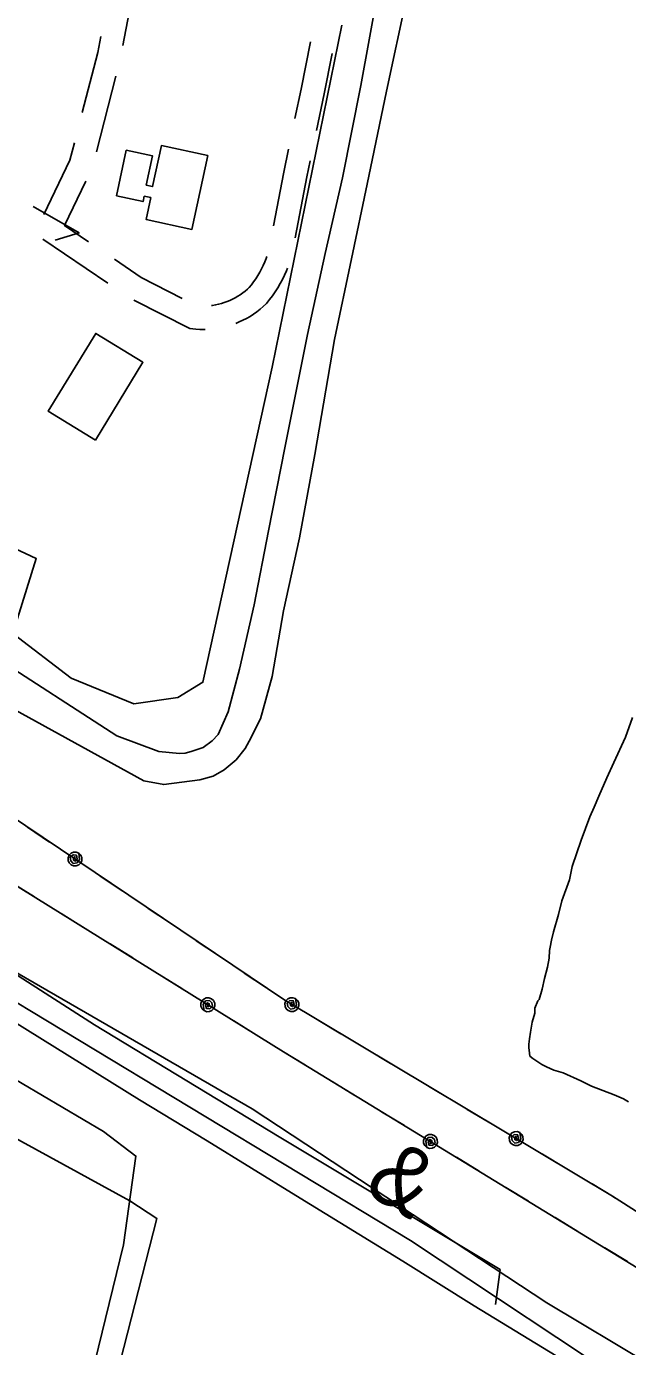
# Model space of a CAD drawing. Extents: x 3355677 to 3393573, y 612928 to 638357.
# Drawn here: x 3365699 to 3366468, y 627611 to 629298 of the extents above; entities that cross this region are included whole.
import ezdxf

# ---------------------------------------------------------------- set-up
doc = ezdxf.new("R2010")
doc.units = 0
for name, color, linetype in [('V-BLDG-OTLN', 7, 'Continuous'), ('V-RAIL-IDEN', 7, 'Continuous'), ('V-RAIL-TRAK', 7, 'Continuous'), ('V-ROAD-CNTR', 7, 'Continuous'), ('V-SITE-OTLN', 7, 'Continuous'), ('V-SITE-VEGE', 7, 'Continuous'), ('V-TOPO-SHOR', 7, 'Continuous'), ('V-UTIL-LINE', 7, 'Continuous')]:
    doc.layers.add(name, color=color, linetype=linetype)

msp = doc.modelspace()

# ---------------------------------------------------------------- linework, layer by layer
at = {"layer": 'V-BLDG-OTLN'}
for points in [[(3365814, 629081.9), (3365826.6, 629140.2), (3365860.4, 629132.9), (3365852.3, 629095.6), (3365860.3, 629093.8), (3365871.7, 629146.1), (3365930.9, 629133.3), (3365910.5, 629039), (3365851.9, 629051.7), (3365857.9, 629079.6), (3365849.7, 629081.3), (3365848.2, 629074.5)], [(3365787.1, 628769.8), (3365726.9, 628806.7), (3365787.7, 628906.1), (3365848, 628869.2)]]:
    msp.add_lwpolyline(points, close=True, dxfattribs=at)
at = {"layer": 'V-RAIL-TRAK'}
for points in [[(3365843.5, 627926.6), (3365193.4, 628330.6), (3364528.2, 628738.8), (3364216.4, 628928.8), (3364132.2, 628979.5)], [(3366499.2, 627524.5), (3366393.7, 627589), (3366271.7, 627663.7), (3366180.2, 627720.6), (3366043.4, 627804.5), (3365929.9, 627874.5), (3365843.5, 627926.6)]]:
    msp.add_lwpolyline(points, dxfattribs=at)
at = {"layer": 'V-ROAD-CNTR'}
for p, q in [((3365788.4, 629138.1), (3365813.4, 629235)), ((3365802.9, 628970.4), (3365720.1, 629026.4))]:
    msp.add_line(p, q, dxfattribs=at)
for points in [[(3365822.4, 629273.9), (3365840.6, 629369.7), (3365841.1, 629372.1)], [(3365770.4, 629188.5), (3365790.2, 629265), (3365794.1, 629285.6)], [(3366062.3, 629278.7), (3366050.2, 629218.1), (3366042.3, 629180.7)], [(3366089.9, 629263.6), (3366079.6, 629212.1), (3366069.9, 629165.6)], [(3365721.3, 629058.1), (3365754.7, 629127.6), (3365760.4, 629149.8)], [(3366034.2, 629141.5), (3366028, 629112.2), (3366014.9, 629043.4)], [(3366061.7, 629126.5), (3366057.5, 629106.3), (3366042.5, 629028.3)], [(3365778.5, 629023.2), (3365747.8, 629043.9), (3365775, 629100.6)], [(3365707.4, 629068.1), (3365766.4, 629034.6), (3365735.7, 629025.2)], [(3365898.1, 628950.9), (3365845.7, 628977.7), (3365811.6, 629000.8)], [(3366006.3, 629004.4), (3366005.5, 629002), (3366003.7, 628997.5), (3366001.8, 628993), (3365999.7, 628988.6), (3365997.4, 628984.3), (3365994.9, 628980.1), (3365992.3, 628976), (3365989.5, 628972.1), (3365986.6, 628968.2), (3365983.8, 628964.9), (3365981.5, 628962.7), (3365978.6, 628960.2), (3365975.6, 628957.8), (3365972.5, 628955.6), (3365969.2, 628953.5), (3365966, 628951.5), (3365962.6, 628949.8), (3365959.1, 628948.1), (3365955.6, 628946.7), (3365952, 628945.4), (3365948.3, 628944.2), (3365944.6, 628943.3), (3365940.9, 628942.5), (3365937.1, 628941.9), (3365935.8, 628941.7)], [(3366032.8, 628989.6), (3366031.5, 628986.1), (3366029.1, 628980.5), (3366026.4, 628975), (3366023.6, 628969.7), (3366020.5, 628964.4), (3366017.2, 628959.3), (3366013.7, 628954.3), (3366010, 628949.5), (3366005.8, 628944.4), (3366001.6, 628940.4), (3365997.7, 628937), (3365993.6, 628933.8), (3365989.4, 628930.8), (3365985, 628927.9), (3365980.5, 628925.3), (3365975.9, 628922.9), (3365971.2, 628920.7), (3365966.7, 628918.8)], [(3365927.7, 628911.1), (3365925.8, 628911), (3365920.6, 628911.1), (3365915.4, 628911.5), (3365907.8, 628912.3), (3365836.5, 628948.7)], [(3365413.6, 628007.8), (3365424.1, 628030.9), (3365443.6, 628076.1), (3365465.8, 628078.1), (3365504.1, 628059.4), (3365615.1, 627993.6), (3365797.7, 627886.5), (3365839, 627854.8), (3365823.1, 627741.6), (3365759, 627479.8), (3365705.6, 627265.5), (3365656.9, 627059.9), (3365561.6, 626679.7), (3365525.3, 626552.8)]]:
    msp.add_lwpolyline(points, dxfattribs=at)
at = {"layer": 'V-SITE-OTLN'}
for points in [[(3366102.4, 629299.9), (3366013, 628862.9), (3365924.7, 628460.4), (3365892.5, 628440.8), (3365836.3, 628432.9), (3365756.1, 628465.5), (3365681.4, 628522.5), (3365711.5, 628618.4), (3365663.9, 628640.5), (3365602.5, 628542.5), (3365338.5, 628679.9), (3365195.8, 628738.5), (3365041.2, 628827), (3364831.4, 628932.6), (3364728.8, 628986.2)], [(3364649.5, 628537.3), (3364827.1, 628446.2), (3365027.5, 628328.8), (3365312.1, 628147.7), (3365299.3, 628050.2), (3365340.5, 628030.5), (3365392.1, 628011.9), (3365413.5, 628007.6), (3365441, 628001.3), (3365607.5, 627919.9), (3365831, 627797.8), (3365865.7, 627775.3), (3365711.4, 627172.4)]]:
    msp.add_lwpolyline(points, dxfattribs=at)
at = {"layer": 'V-SITE-VEGE'}
for points in [[(3366489.6, 627548.7), (3366190.1, 627747), (3365625.5, 628087.7), (3365112.6, 628404.6), (3365091.1, 628419.7), (3365086.8, 628430.5), (3365093.2, 628434.8), (3365110.5, 628430.5), (3365136.3, 628421.9), (3365157.9, 628408.9), (3365188, 628385.2), (3365257, 628337.8), (3365317.3, 628303.3), (3365354, 628281.7), (3365442.3, 628238.6), (3365670.7, 628098.5), (3365987.5, 627915.2), (3366364.6, 627667.3), (3366894.7, 627350.3)], [(3366468.9, 627924.4), (3366462.6, 627928.1), (3366450.4, 627933.3), (3366421.4, 627944.3), (3366407.7, 627951.1), (3366385.5, 627961.1), (3366373.4, 627964.8), (3366363.9, 627969), (3366358, 627972.1), (3366346.4, 627979.5), (3366342.7, 627982.6), (3366342.2, 627986.3), (3366341.6, 627993.7), (3366341.6, 627997.9), (3366342.1, 628004.8), (3366343.7, 628013.2), (3366345.8, 628025.9), (3366348.9, 628037.5), (3366348.9, 628043.8), (3366353.1, 628053.4), (3366354.7, 628054.9), (3366358.3, 628068.1), (3366361.5, 628081.9), (3366365.1, 628096.1), (3366367.2, 628107.7), (3366367.7, 628117.7), (3366368.8, 628122), (3366370.3, 628130.9), (3366372.9, 628141.5), (3366379.2, 628163.7), (3366383.4, 628181.1), (3366393.4, 628208), (3366397, 628224.9), (3366408.5, 628258.7), (3366419.6, 628288.2), (3366424.8, 628300.9), (3366431.1, 628314.7), (3366441.1, 628338.4), (3366450, 628358), (3366465.2, 628390.2), (3366474.1, 628415.5)]]:
    msp.add_lwpolyline(points, dxfattribs=at)
at = {"layer": 'V-TOPO-SHOR'}
for points in [[(3365814.7, 628391.7), (3365868.5, 628371.7), (3365894.7, 628369.3), (3365902.1, 628369.6), (3365909.5, 628371.8), (3365925.1, 628377.1), (3365936.7, 628385.3), (3365944.1, 628393.4), (3365956.8, 628422.4), (3365971.5, 628476.9), (3365990.4, 628559.3), (3366008.6, 628653.8), (3366029.2, 628759.9), (3366058.5, 628904.9), (3366080.9, 629008.2), (3366103, 629105.1), (3366126.4, 629222.9), (3366148.7, 629344.9)], [(3365849.2, 628334.2), (3365874.6, 628329.6), (3365920.6, 628335.7), (3365937.9, 628340.4), (3365952, 628348.5), (3365967.2, 628361.3), (3365978.8, 628375.5), (3365983.7, 628385), (3365998.2, 628413.7), (3366013.3, 628467.5), (3366027.9, 628551.7), (3366048.2, 628645), (3366067.7, 628751.5), (3366092.9, 628898.3), (3366114.5, 629001.2), (3366134.8, 629096.7), (3366159.6, 629215.5), (3366185.5, 629336.9)], [(3365814.7, 628391.7), (3365653.3, 628495.9), (3365552.9, 628550.3), (3365487.1, 628582.3), (3365483.9, 628572.7), (3365470.9, 628534.6), (3365477.1, 628531.5), (3365651.5, 628442.8), (3365849.2, 628334.2)], [(3365415, 628272.5), (3365437.5, 628248.2), (3365596.4, 628144.1), (3365786.1, 628022.4), (3366022.3, 627879.6), (3366304.6, 627709.8), (3366298.7, 627665.3)]]:
    msp.add_lwpolyline(points, dxfattribs=at)
at = {"layer": 'V-UTIL-LINE'}
for points in [[(3370599.1, 625159.7), (3369954, 625561.1), (3369433, 625883.7), (3369003.6, 626135.6), (3368625.6, 626361.6), (3368231.9, 626619.3), (3367851.3, 626850.7), (3367382.4, 627145.7), (3366865, 627444.4), (3366480, 627712.3), (3366027.6, 627988.3), (3365574.4, 628269.8), (3365118.6, 628541.7), (3364545.7, 628879.7), (3364115.5, 629158.1), (3363633, 629456.1), (3363159.7, 629754.2), (3362684.9, 630044.1), (3362215.7, 630326.1), (3361710.6, 630626.7), (3361234.6, 630908.5), (3360733.5, 631217), (3359805.2, 631780.2)], [(3360754.9, 631203.8), (3361272.8, 630966.2), (3361739.5, 630687.3), (3362229.5, 630409.9), (3362725.1, 630088.2), (3363192.5, 629799.9), (3363660, 629518.9), (3364148.1, 629221.1), (3365159.2, 628623.7), (3365586.8, 628351.6), (3366029.2, 628054), (3366448.3, 627803.7), (3366902.5, 627514.5), (3367411.9, 627203.2), (3367902.7, 626885.8), (3368361.7, 626578.4)], [(3365700.5, 628275.2), (3365728.7, 628256.2)], [(3365761, 628234.4), (3365761, 628237.3), (3365759.1, 628235.9), (3365759.2, 628233.2), (3365761.8, 628231.8), (3365763.8, 628234.6), (3365763, 628239.2), (3365758.8, 628239.9), (3365755.1, 628236.7), (3365755.8, 628232.2), (3365758.9, 628228.9), (3365763.7, 628229.4), (3365767, 628233.8), (3365766, 628241.9), (3365762.8, 628243.2), (3365759.3, 628243.2), (3365756, 628241.9), (3365753.6, 628239.4), (3365752.2, 628236.2), (3365752.2, 628232.7), (3365753.5, 628229.4), (3365756, 628226.9), (3365759.2, 628225.6), (3365762.7, 628225.6), (3365766, 628226.9), (3365768.5, 628229.4), (3365769.8, 628232.6), (3365769.9, 628236.1), (3365768.5, 628239.4), (3365766, 628241.9)], [(3365793.4, 628212.6), (3365821.6, 628193.7)], [(3365709.2, 628186), (3365680.3, 628204)], [(3365772.1, 628147), (3365743.2, 628164.9)], [(3365854.8, 628171.3), (3365883, 628152.3)], [(3365834.9, 628108), (3365806, 628125.9)], [(3365916.2, 628130), (3365944.4, 628111)], [(3365977.6, 628088.7), (3366005.8, 628069.7)], [(3365897.8, 628068.9), (3365868.9, 628086.8)], [(3365930.9, 628048.3), (3365931.1, 628045.5), (3365932.9, 628046.9), (3365932.7, 628049.6), (3365930.1, 628050.9), (3365928.1, 628048.1), (3365929.1, 628043.5), (3365933.3, 628043), (3365936.9, 628046.3), (3365936.1, 628050.8), (3365932.9, 628053.9), (3365928.1, 628053.2), (3365924.9, 628048.7), (3365926.2, 628040.7), (3365929.5, 628039.4), (3365933, 628039.6), (3365936.2, 628041), (3365938.6, 628043.6), (3365939.8, 628046.9), (3365939.7, 628050.4), (3365938.2, 628053.6), (3365935.7, 628056), (3365932.4, 628057.2), (3365928.9, 628057.1), (3365925.7, 628055.6), (3365923.3, 628053.1), (3365922, 628049.8), (3365922.2, 628046.3), (3365923.6, 628043.1), (3365926.2, 628040.7)], [(3366038.4, 628048.4), (3366038.2, 628051.3), (3366036.4, 628049.8), (3366036.7, 628047.1), (3366039.3, 628045.9), (3366041.2, 628048.7), (3366040.2, 628053.3), (3366035.9, 628053.8), (3366032.4, 628050.4), (3366033.3, 628045.9), (3366036.6, 628042.8), (3366041.3, 628043.6), (3366044.4, 628048.1), (3366043, 628056.2), (3366039.7, 628057.3), (3366036.2, 628057.2), (3366033.1, 628055.7), (3366030.7, 628053.1), (3366029.5, 628049.7), (3366029.7, 628046.2), (3366031.2, 628043.1), (3366033.8, 628040.7), (3366037.1, 628039.5), (3366040.6, 628039.7), (3366043.8, 628041.2), (3366046.2, 628043.8), (3366047.3, 628047.1), (3366047.2, 628050.6), (3366045.7, 628053.8), (3366043, 628056.2)], [(3365992.9, 628009.8), (3365964, 628027.8)], [(3366071.9, 628028.4), (3366101.1, 628011)], [(3366055.9, 627971), (3366027.6, 627988.3), (3366026.9, 627988.7)], [(3366135.5, 627990.5), (3366164.6, 627973.1)], [(3366119.1, 627932.5), (3366090.1, 627950.2)], [(3366199, 627952.6), (3366228.2, 627935.1)], [(3366182.3, 627893.9), (3366153.2, 627911.6)], [(3366262.5, 627914.6), (3366291.7, 627897.2)], [(3366215.6, 627873.6), (3366215.7, 627870.7), (3366217.6, 627872.2), (3366217.3, 627874.9), (3366214.7, 627876.2), (3366212.8, 627873.3), (3366213.8, 627868.8), (3366218, 627868.3), (3366221.6, 627871.6), (3366220.7, 627876.1), (3366217.5, 627879.2), (3366212.7, 627878.5), (3366209.6, 627874), (3366210.9, 627865.9), (3366214.2, 627864.7), (3366217.7, 627864.9), (3366220.9, 627866.3), (3366223.3, 627868.9), (3366224.5, 627872.2), (3366224.3, 627875.7), (3366222.8, 627878.9), (3366220.3, 627881.3), (3366217, 627882.5), (3366213.5, 627882.4), (3366210.3, 627880.9), (3366207.9, 627878.3), (3366206.7, 627875), (3366206.8, 627871.5), (3366208.3, 627868.3), (3366210.9, 627865.9)], [(3366325.2, 627877.2), (3366325, 627880.1), (3366323.2, 627878.6), (3366323.4, 627875.9), (3366326.1, 627874.7), (3366328, 627877.5), (3366327, 627882.1), (3366322.7, 627882.5), (3366319.2, 627879.2), (3366320.1, 627874.7), (3366323.3, 627871.6), (3366328.1, 627872.3), (3366331.2, 627876.9), (3366329.8, 627884.9), (3366326.5, 627886.1), (3366323, 627885.9), (3366319.8, 627884.4), (3366317.5, 627881.8), (3366316.3, 627878.5), (3366316.5, 627875), (3366318, 627871.8), (3366320.6, 627869.5), (3366323.9, 627868.3), (3366327.4, 627868.5), (3366330.6, 627870), (3366332.9, 627872.6), (3366334.1, 627875.9), (3366333.9, 627879.4), (3366332.4, 627882.6), (3366329.8, 627884.9)], [(3366277.9, 627835.6), (3366248.9, 627853.3)], [(3366358.7, 627857.2), (3366387.9, 627839.8)], [(3366422.2, 627819.3), (3366448.3, 627803.7), (3366451.4, 627801.7)], [(3366341.1, 627797.1), (3366312, 627814.8)], [(3366404.2, 627758.5), (3366375.2, 627776.2)], [(3366467.4, 627720), (3366438.4, 627737.7)]]:
    msp.add_lwpolyline(points, dxfattribs=at)

# ---------------------------------------------------------------- texts
at = {"layer": 'V-RAIL-IDEN'}
msp.add_text('&', height=83, rotation=329.2261, dxfattribs=at).set_placement((3366128.3, 627810.3))

doc.saveas('drawing.dxf')
